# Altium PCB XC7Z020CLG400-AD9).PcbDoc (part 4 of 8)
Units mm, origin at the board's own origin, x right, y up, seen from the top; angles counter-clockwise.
Board outline 38 x 38 mm, 14 copper layers (Top Layer, GND02, ART03, PWR04, ART05, GND06, ART07, ART08, PWR09, ART10, GND11, ART12, PWR13, Bottom Layer); 276 components, 302 nets, 1684 pads, 1576 vias.
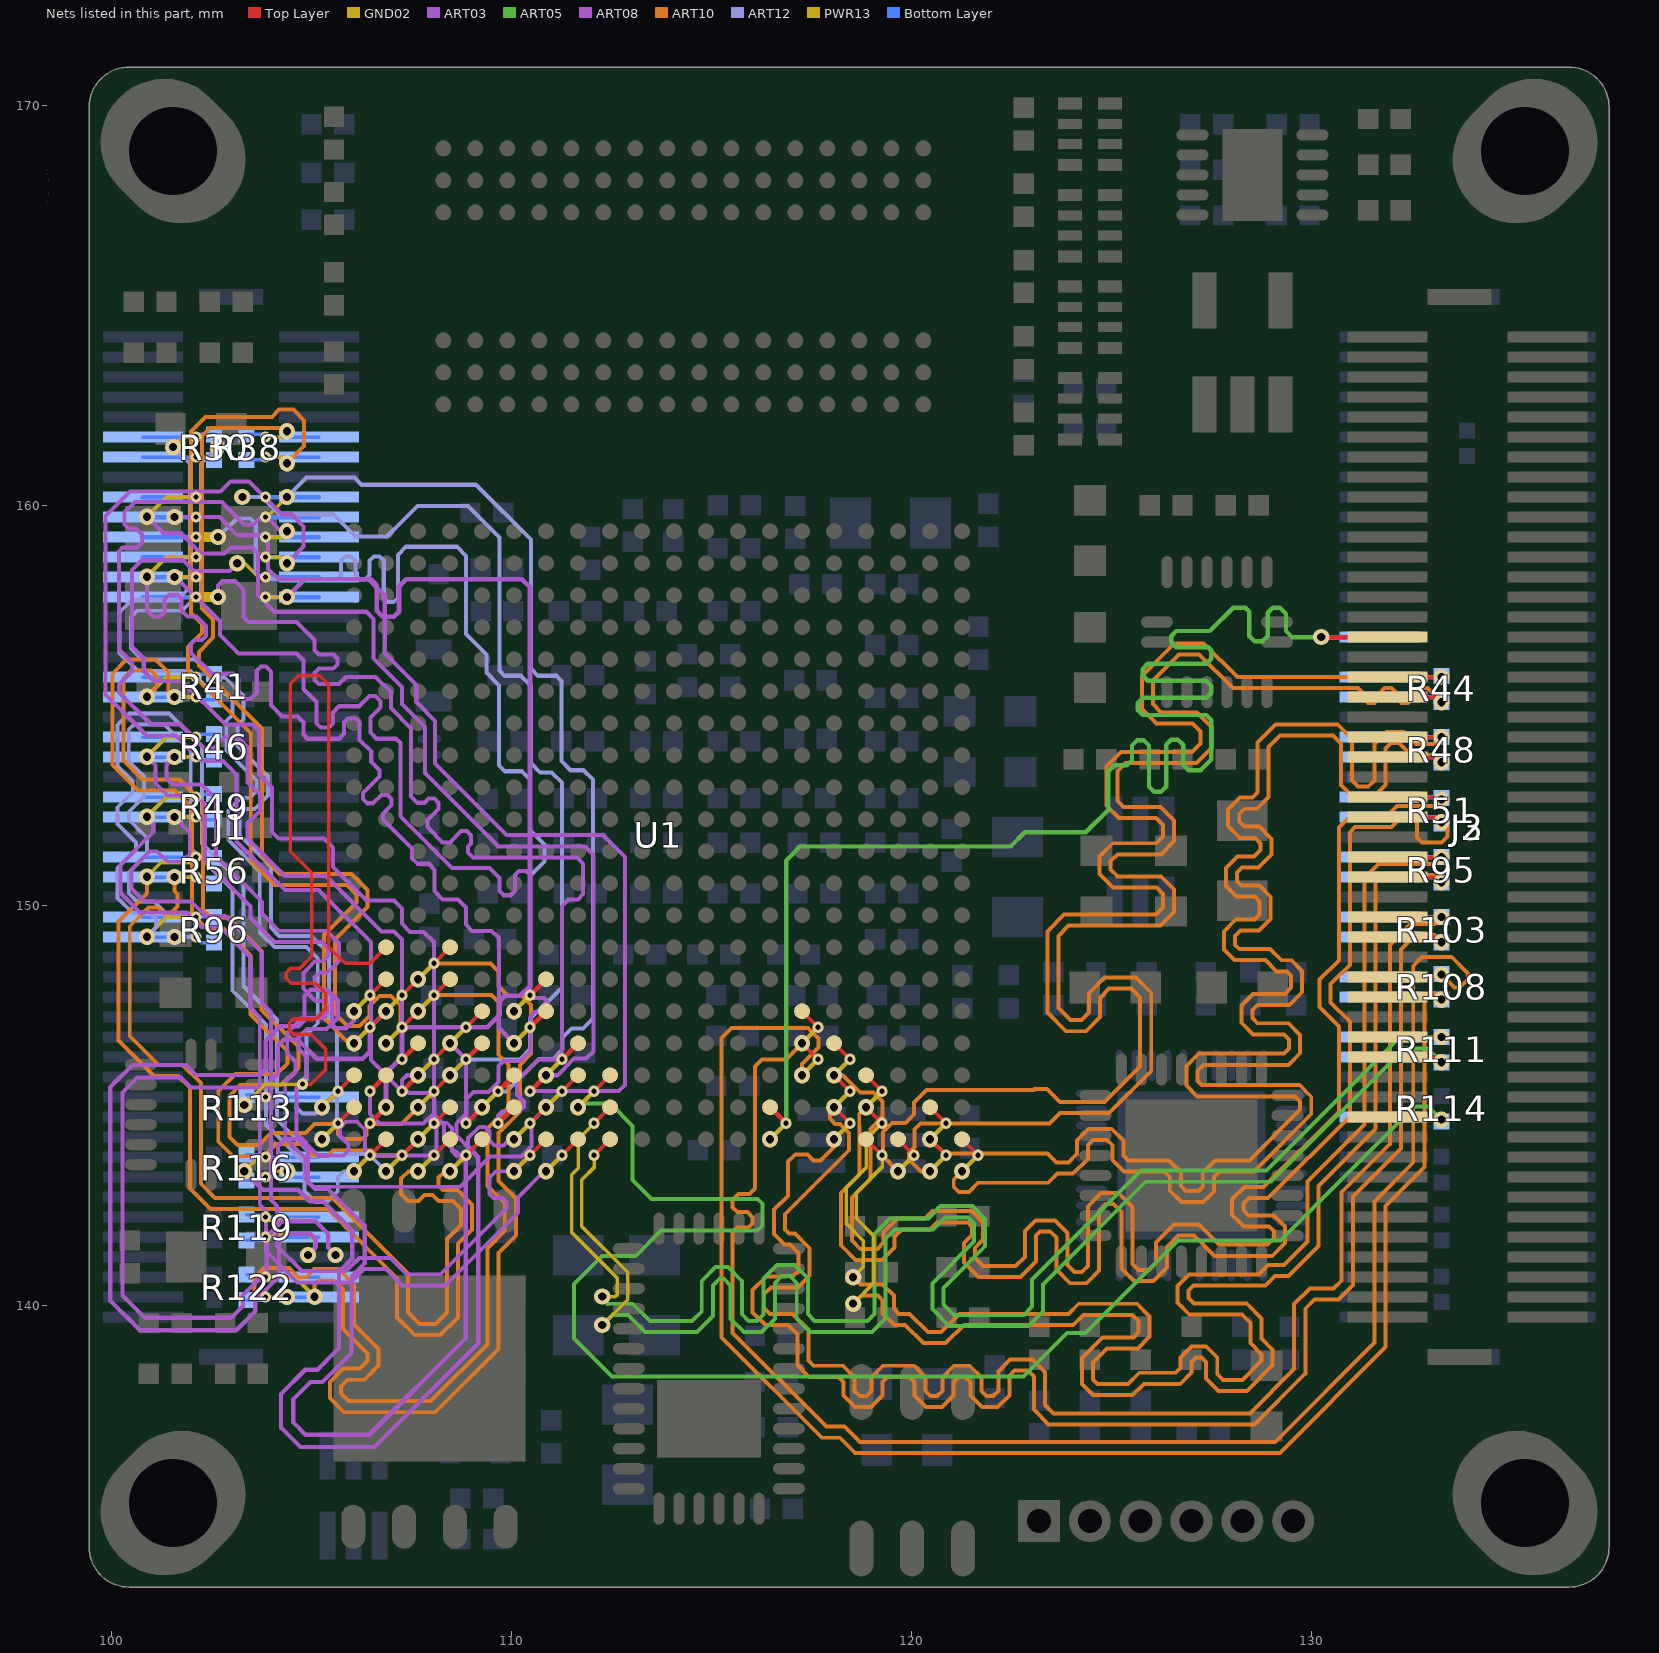
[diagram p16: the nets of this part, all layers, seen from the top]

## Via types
v1: diameter 0.406, hole 0.203, GND02 to PWR13, 466 vias
v2: diameter 0.279, hole 0.127, Top Layer to GND02, tented top, 373 vias
v3: diameter 0.406, hole 0.203, Top Layer to Bottom Layer, 324 vias
v4: diameter 0.279, hole 0.127, PWR13 to Bottom Layer, 207 vias
v5: diameter 0.279, hole 0.127, Top Layer to ART03, tented top, 41 vias
v6: diameter 0.279, hole 0.127, Top Layer to ART03, 40 vias
v7: diameter 0.279, hole 0.127, PWR13 to Bottom Layer, tented bottom, 39 vias
v8: diameter 0.279, hole 0.127, ART12 to Bottom Layer, 30 vias
v9: diameter 0.279, hole 0.127, Top Layer to GND02, 20 vias
v10: diameter 0.406, hole 0.203, Top Layer to Bottom Layer, tented both sides, 16 vias
v11: diameter 0.406, hole 0.203, ART03 to ART12, 11 vias
v12: diameter 0.406, hole 0.203, Top Layer to Bottom Layer, tented top, 9 vias

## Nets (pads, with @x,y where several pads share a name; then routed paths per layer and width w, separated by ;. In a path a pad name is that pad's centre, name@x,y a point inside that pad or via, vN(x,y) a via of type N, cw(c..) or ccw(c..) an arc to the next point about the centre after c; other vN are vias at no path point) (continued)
B34_L8_P: J1.89 R113.1 U1.W14 | length 26.9
  Top Layer w0.089: v9(104.775,145.542) 104.985,145.542 105.362,145.918 ; 105.16,145.716 105.362,145.918 ; U1.W14@106.865,148.965 106.465,148.565 105.842,148.565 105.435,148.971 105.435,155.524 105.207,155.753 104.673,155.753 104.47,155.55 104.47,151.366 105.006,150.83 105.006,148.738 104.703,148.435 104.475,148.435 104.371,148.331 104.371,148.188 104.496,148.064 105.105,148.064 105.358,147.811 105.358,147.421 105.11,147.172 104.551,147.172 104.448,147.07 104.448,146.899 104.554,146.794 104.978,146.794 105.362,146.41 105.362,145.918
  GND02 w0.089: v1(103.32,145.022) 103.841,145.542 v9(104.775,145.542)
  PWR13 w0.089: v1(103.32,145.022) 103.518,145.219 v4(103.853,145.219)
  Bottom Layer w0.089: R113.1@103.378,145.278 103.794,145.278 v4(103.853,145.219) J1.89@105.182,145.219
B34_L9_N: J1.93 R116.2 U1.U17 | length 27
  Top Layer w0.089: v2(108.065,146.165) U1.U17@108.465,146.565
  GND02 w0.109: v1(107.665,145.765) v2(108.065,146.165)
  ART08 w0.107: v1(104.4,143.365) 104.165,143.6 104.165,143.993 104.343,144.17 104.648,144.17 104.907,143.912 104.907,143.105 105.086,142.926 105.416,142.926 106.329,142.013 106.329,141.058 105.999,140.728 105.999,138.816 105.278,138.095 104.973,138.095 104.546,137.668 104.546,137.084 104.851,136.779 106.445,136.779 108.859,139.193 108.859,143.591 108.316,144.135 108.316,144.516 108.077,144.755 108.077,145.161 107.915,145.323 107.432,145.323 107.264,145.491 107.264,145.644 107.386,145.765 v1(107.665,145.765)
  PWR13 w0.089: v4(103.853,143.219) 103.999,143.365 v1(104.4,143.365)
  Bottom Layer w0.089: R116.2@103.378,143.139 103.773,143.139 v4(103.853,143.219) J1.93@105.182,143.219
B34_L9_P: J1.92 R116.1 U1.T16 | length 27
  Top Layer w0.089: v2(108.865,146.965) U1.T16@109.265,147.365
  GND02 w0.109: v1(108.465,146.565) v2(108.865,146.965)
  ART08 w0.107: v1(103.32,143.365) 103.78,142.905 104.669,142.905 104.958,142.616 105.288,142.616 106.02,141.884 106.02,141.186 105.75,140.917 105.706,140.917 105.689,140.9 105.689,138.944 105.15,138.405 104.845,138.405 104.237,137.796 104.237,136.955 104.723,136.469 106.573,136.469 109.169,139.065 109.169,143.72 108.626,144.263 108.626,144.556 108.864,144.795 108.864,146.166 v1(108.465,146.565)
  PWR13 w0.089: v1(103.32,143.365) 103.675,143.719 v4(103.853,143.719)
  Bottom Layer w0.089: R116.1@103.378,143.779 103.793,143.779 v4(103.853,143.719) J1.92@105.182,143.719
B34_L10_N: J1.96 R119.2 U1.W15 | length 26.9
  Top Layer w0.089: v2(106.465,147.765) U1.W15@106.865,148.165
  GND02 w0.109: v1(106.065,147.365) v2(106.465,147.765)
  ART08 w0.107: v1(104.914,141.275) 105.105,141.466 105.105,141.675 104.977,141.803 104.389,141.803 104.191,141.605 104.191,140.735 103.597,140.141 103.597,139.868 103.119,139.39 100.71,139.39 99.967,140.133 99.967,145.465 100.522,146.02 101.865,146.02 102.114,145.771 103.703,145.771 103.856,145.923 103.856,146.636 104.21,146.99 104.673,146.99 104.826,147.142 104.826,147.752 104.978,147.904 105.359,147.904 105.512,147.752 105.512,147.041 105.613,146.939 105.867,146.939 106.065,147.137 v1(106.065,147.365)
  PWR13 w0.089: v4(103.853,141.719) 103.932,141.798 104.926,141.798 105.087,141.637 105.087,141.448 v1(104.914,141.275)
  Bottom Layer w0.089: R119.2@103.378,141.641 103.774,141.641 v4(103.853,141.719) J1.96@105.182,141.719
B34_L10_P: J1.95 R119.1 U1.V15 | length 26.9
  Top Layer w0.089: v2(107.265,147.765) U1.V15@107.665,148.165
  GND02 w0.109: v1(106.865,147.365) v2(107.265,147.765)
  ART08 w0.107: v1(105.602,141.275) 105.415,141.462 105.415,141.803 105.105,142.113 104.261,142.113 103.881,141.733 103.881,140.863 103.287,140.27 103.287,139.997 102.991,139.7 100.838,139.7 100.277,140.261 100.277,145.336 100.651,145.71 101.736,145.71 101.986,145.461 103.831,145.461 104.165,145.795 104.165,146.507 104.318,146.66 104.648,146.66 105.131,146.177 106.274,146.177 106.451,146.355 106.451,146.951 v1(106.865,147.365)
  PWR13 w0.089: v4(103.853,142.219) 103.932,142.141 105.068,142.141 105.43,141.779 105.43,141.448 v1(105.602,141.275)
  Bottom Layer w0.089: R119.1@103.378,142.281 103.792,142.281 v4(103.853,142.219) J1.95@105.182,142.219
B34_L11_N: J1.99 R122.2 U1.U15 | length 27.1
  Top Layer w0.089: v2(108.065,147.765) U1.U15@108.465,148.165
  ART10 w0.099: v1(104.391,140.219) 103.722,140.219 103.581,140.36 103.581,140.716 103.81,140.945 104.445,140.945 104.673,140.716 104.866,140.716 105.067,140.917 105.677,140.917 106.068,140.526 106.068,139.535 106.68,138.923 106.68,138.506 106.327,138.153 105.906,138.153 105.738,137.985 105.738,137.808 105.929,137.617 107.975,137.617 109.398,139.04 109.398,141.438 109.832,141.872 109.832,142.568 109.398,143.002 109.398,144.435 109.931,144.968 109.931,146.025 ; v1(107.665,147.365) 108.077,147.777 109.499,147.777 109.677,147.599 109.677,146.279 109.931,146.025 ; 109.931,145.999 109.931,146.025
  GND02 w0.109: v1(107.665,147.365) v2(108.065,147.765)
  PWR13 w0.102: v4(103.853,140.219) v1(104.391,140.219)
  Bottom Layer w0.089: R122.2@103.378,140.142 103.776,140.142 v4(103.853,140.219) J1.99@105.182,140.219
B34_L11_P: J1.98 R122.1 U1.U14 | length 27.1
  Top Layer w0.089: v2(108.065,148.565) U1.U14@108.465,148.965
  ART10 w0.099: v1(105.079,140.23) 105.079,140.537 105.181,140.64 105.562,140.64 105.791,140.411 105.791,139.421 106.403,138.808 106.403,138.621 106.212,138.43 105.791,138.43 105.461,138.1 105.461,137.693 105.814,137.34 108.09,137.34 109.675,138.925 109.675,141.323 110.109,141.757 110.109,142.682 109.675,143.117 109.675,144.32 110.208,144.854 110.208,146.025 110.49,146.307 110.49,147.523 110.261,147.752 109.916,147.752 109.677,147.991 109.677,148.361 109.474,148.565 v2(108.065,148.565) v1(107.665,148.165)
  GND02 w0.109: v1(107.665,148.165) v2(108.065,148.565)
  PWR13 w0.102: v4(103.853,140.719) 104.589,140.719 v1(105.079,140.23)
  Bottom Layer w0.089: R122.1@103.378,140.782 103.79,140.782 v4(103.853,140.719) J1.98@105.182,140.719
B34_L12_N: J1.19 R41.2 U1.U19 | length 27.1
  Top Layer w0.089: v2(108.065,144.565) U1.U19@108.465,144.965
  ART10 w0.099: v1(101.573,155.219) 101.42,155.373 101.42,155.842 101.105,156.157 100.378,156.157 100.025,155.804 100.025,153.518 100.66,152.883 101.589,152.883 102.009,152.463 102.009,149.796 102.374,149.431 102.806,149.431 103.478,148.759 103.478,147.285 104.397,146.367 104.397,146.063 104.127,145.793 103.096,145.793 102.669,145.367 102.669,144.107 103.035,143.741 103.797,143.741 104.1,144.043 104.775,144.043 105.054,143.764 105.41,143.764 105.537,143.891 106.502,143.891 106.629,143.764 107.264,143.764 v1(107.665,144.165)
  GND02 w0.109: v1(107.665,144.165) v2(108.065,144.565)
  PWR13 w0.102: v1(101.573,155.219) v4(102.111,155.219)
  Bottom Layer w0.089: J1.19@100.782,155.219 v4(102.111,155.219) 102.177,155.153 R41.2@102.565,155.153
B34_L12_P: J1.18 R41.1 U1.U18 | length 27
  Top Layer w0.089: v2(108.065,145.365) U1.U18@108.465,145.765
  ART10 w0.099: v1(100.885,155.23) 101.143,155.487 101.143,155.727 100.99,155.88 100.493,155.88 100.302,155.689 100.302,153.632 100.775,153.159 101.704,153.159 102.286,152.578 102.286,149.911 102.489,149.708 102.921,149.708 103.755,148.873 103.755,147.4 104.673,146.482 104.673,145.948 104.242,145.517 103.211,145.517 102.946,145.252 102.946,144.221 103.149,144.018 103.683,144.018 103.985,144.32 104.849,144.32 105.08,144.551 105.512,144.551 105.664,144.399 105.664,144.297 105.794,144.168 106.271,144.168 106.375,144.272 106.375,144.45 106.477,144.551 107.251,144.551 v1(107.665,144.965)
  GND02 w0.109: v1(107.665,144.965) v2(108.065,145.365)
  PWR13 w0.102: v1(100.885,155.23) 101.375,155.719 v4(102.111,155.719)
  Bottom Layer w0.089: J1.18@100.782,155.719 v4(102.111,155.719) 102.185,155.793 R41.1@102.565,155.793
B34_L13_N: J1.22 R46.2 U1.P19 | length 27
  Top Layer w0.089: v2(110.465,144.565) U1.P19@110.865,144.965
  ART03 w0.097: v1(101.573,153.719) 101.378,153.524 101.378,153.181 101.524,153.035 102.249,153.035 102.616,152.668 102.616,151.246 103.759,150.103 103.759,149.809 104.191,149.377 105.373,149.377 105.689,149.061 105.689,148.627 105.399,148.336 105.207,148.336 105.08,148.209 105.08,148.045 105.221,147.904 105.399,147.904 105.664,147.639 105.664,147.204 105.378,146.918 104.881,146.918 104.673,146.71 104.673,146.431 104.877,146.228 104.877,145.731 104.623,145.477 104.623,144.308 105.167,143.764 105.8,143.764 105.924,143.888 105.924,144.037 105.715,144.247 105.715,144.45 105.867,144.602 106.138,144.602 106.338,144.402 106.338,143.888 106.463,143.764 108.026,143.764 108.128,143.866 108.128,144.475 108.229,144.577 108.382,144.577 108.509,144.45 108.509,143.866 108.61,143.764 108.788,143.764 108.915,143.891 108.915,144.196 109.195,144.475 109.345,144.475 109.449,144.372 109.449,144.137 109.576,144.01 109.796,144.01 109.951,144.165 v1(110.065,144.165)
  GND02 w0.109: v1(110.065,144.165) v2(110.465,144.565)
  PWR13 w0.102: v1(101.573,153.719) v4(102.111,153.719)
  Bottom Layer w0.089: J1.22@100.782,153.719 v4(102.111,153.719) 102.175,153.655 R46.2@102.565,153.655
B34_L13_P: J1.21 R46.1 U1.N18 | length 27
  Top Layer w0.089: v2(111.265,145.365) U1.N18@111.665,145.765
  ART03 w0.097: v1(100.885,153.73) 101.099,153.516 101.099,153.065 101.408,152.756 102.133,152.756 102.337,152.552 102.337,151.13 103.48,149.987 103.48,149.693 104.075,149.098 105.258,149.098 105.41,148.946 105.41,148.742 105.283,148.615 105.091,148.615 104.8,148.325 104.8,147.93 105.105,147.625 105.283,147.625 105.385,147.523 105.385,147.32 105.262,147.197 104.765,147.197 104.394,146.826 104.394,146.315 104.597,146.112 104.597,145.847 104.343,145.593 104.343,144.192 104.851,143.684 104.851,143.18 105.054,142.977 108.712,142.977 109.466,143.731 110.245,143.731 110.499,143.985 110.499,144.345 110.497,144.347 110.497,144.597 v1(110.865,144.965)
  GND02 w0.109: v1(110.865,144.965) v2(111.265,145.365)
  PWR13 w0.102: v1(100.885,153.73) 101.375,154.219 v4(102.111,154.219)
  Bottom Layer w0.089: J1.21@100.782,154.219 v4(102.111,154.219) 102.187,154.295 R46.1@102.565,154.295
B34_L14_N: J1.25 R49.2 U1.P20 | length 27
  Top Layer w0.089: v2(110.465,143.765) U1.P20@110.865,144.165
  ART03 w0.097: v1(101.573,152.219) 101.956,151.837 101.956,151.282 101.778,151.105 101.397,151.105 101.143,151.359 100.954,151.359 100.502,150.907 100.502,150.439 100.827,150.114 101.995,150.114 102.363,149.746 102.841,149.746 103.759,148.828 103.759,147.574 103.988,147.345 103.988,142.646 104.14,142.494 104.14,141.492 104.764,140.868 105.867,140.868 106.197,141.199 106.974,141.199 107.38,140.792 108.229,140.792 109.88,142.443 109.88,142.596 109.779,142.697 109.55,142.697 109.449,142.799 109.449,143.205 109.608,143.365 v1(110.065,143.365)
  GND02 w0.109: v1(110.065,143.365) v2(110.465,143.765)
  PWR13 w0.102: v1(101.573,152.219) v4(102.111,152.219)
  Bottom Layer w0.089: J1.25@100.782,152.219 v4(102.111,152.219) 102.174,152.156 R49.2@102.565,152.156
B34_L14_P: J1.24 R49.1 U1.N20 | length 27.1
  Top Layer w0.089: v2(111.265,143.765) U1.N20@111.665,144.165
  ART03 w0.097: v1(100.885,152.23) 101.041,152.073 101.041,151.841 100.223,151.023 100.223,150.323 100.711,149.835 101.879,149.835 102.248,149.466 102.725,149.466 103.48,148.712 103.48,147.458 103.708,147.23 103.708,142.531 103.861,142.378 103.861,141.376 104.648,140.589 105.983,140.589 106.313,140.919 106.858,140.919 107.264,140.513 108.345,140.513 110.16,142.327 110.16,142.708 110.816,143.365 v1(110.865,143.365)
  GND02 w0.109: v1(110.865,143.365) v2(111.265,143.765)
  PWR13 w0.102: v1(100.885,152.23) 101.375,152.719 v4(102.111,152.719)
  Bottom Layer w0.089: J1.24@100.782,152.719 v4(102.111,152.719) 102.188,152.796 R49.1@102.565,152.796
B34_L15_N: J1.28 R56.2 U1.U20 | length 27
  Top Layer w0.089: v2(108.065,143.765) U1.U20@108.465,144.165
  ART10 w0.099: v1(101.573,150.719) 101.573,150.369 101.651,150.292 101.651,149.987 101.473,149.809 101.321,149.809 101.226,149.904 101.168,149.962 100.928,149.962 100.457,149.49 100.457,146.746 101.181,146.022 101.78,146.022 102.235,145.567 102.235,143.053 102.593,142.695 105.525,142.695 107.414,140.805 107.414,139.83 107.696,139.548 108.102,139.548 108.384,139.83 108.384,141.669 108.737,142.022 108.737,142.418 108.534,142.621 108.179,142.621 108.026,142.773 107.823,142.773 107.671,142.621 107.417,142.621 107.239,142.799 107.239,143.18 107.424,143.365 v1(107.665,143.365)
  GND02 w0.109: v1(107.665,143.365) v2(108.065,143.765)
  PWR13 w0.089: v1(101.573,150.719) v4(102.111,150.719)
  Bottom Layer w0.089: J1.28@100.782,150.719 v4(102.111,150.719) 102.274,150.556 R56.2@102.565,150.556
B34_L15_P: J1.27 R56.1 U1.T20 | length 27
  Top Layer w0.089: v2(108.865,143.765) U1.T20@109.265,144.165
  ART10 w0.099: v1(100.885,150.73) 100.885,150.313 100.18,149.609 100.18,146.632 101.067,145.745 101.666,145.745 101.958,145.453 101.958,142.938 102.478,142.418 105.41,142.418 107.137,140.691 107.137,139.715 107.581,139.271 108.217,139.271 108.661,139.715 108.661,141.554 109.014,141.907 109.014,142.532 108.649,142.898 108.293,142.898 108.179,143.013 108.179,143.205 108.338,143.365 v1(108.465,143.365)
  GND02 w0.109: v1(108.465,143.365) v2(108.865,143.765)
  PWR13 w0.089: v1(100.885,150.73) 101.235,151.079 101.971,151.079 v4(102.111,151.219)
  Bottom Layer w0.089: J1.27@100.782,151.219 v4(102.111,151.219) 102.134,151.196 R56.1@102.565,151.196
B34_L16_N: J1.31 R96.2 U1.W20 | length 27
  Top Layer w0.089: v2(106.465,143.765) U1.W20@106.865,144.165
  ART12 w0.097: v1(101.573,149.219) 101.975,149.219 102.083,149.327 102.083,149.657 101.928,149.812 101.369,149.812 101.067,150.114 100.635,150.114 100.432,150.317 100.432,150.836 100.889,151.294 100.889,151.703 100.432,152.16 100.432,152.349 100.813,152.73 100.813,153.238 100.432,153.619 100.432,154.407 100.559,154.534 101.321,154.534 101.981,153.873 101.981,151.446 103.022,150.405 103.022,147.879 103.861,147.041 103.861,144.537 104.826,143.572 104.826,142.875 105.105,142.596 105.385,142.596 105.658,142.869 105.658,143.205 105.817,143.365 v1(106.065,143.365)
  GND02 w0.109: v1(106.065,143.365) v2(106.465,143.765)
  PWR13 w0.102: v1(101.573,149.219) v4(102.111,149.219)
  Bottom Layer w0.089: J1.31@100.782,149.219 v4(102.111,149.219) 102.247,149.083 R96.2@102.565,149.083
B34_L16_P: J1.30 R96.1 U1.V20 | length 27.1
  Top Layer w0.089: v2(107.265,143.765) U1.V20@107.665,144.165
  ART12 w0.097: v1(100.885,149.23) 101.117,149.462 101.117,149.668 100.951,149.835 100.519,149.835 100.152,150.201 100.152,150.952 100.609,151.409 100.609,151.587 100.152,152.044 100.152,152.465 100.533,152.846 100.533,153.122 100.152,153.503 100.152,154.522 100.443,154.813 101.436,154.813 102.26,153.989 102.26,151.562 103.302,150.52 103.302,147.995 104.14,147.156 104.14,144.653 105.029,143.764 105.85,143.764 105.885,143.799 106.431,143.799 v1(106.865,143.365)
  GND02 w0.109: v1(106.865,143.365) v2(107.265,143.765)
  PWR13 w0.102: v1(100.885,149.23) 101.375,149.719 v4(102.111,149.719)
  Bottom Layer w0.089: J1.30@100.782,149.719 v4(102.111,149.719) 102.115,149.723 R96.1@102.565,149.723
B34_L17_N: J1.7 R30.2 U1.Y19 | length 27
  Top Layer w0.089: v2(105.665,144.565) U1.Y19@106.065,144.965
  ART12 w0.097: v1(102.649,161.468) 102.235,161.054 102.235,157.847 101.767,157.378 100.635,157.378 100.482,157.226 100.482,156.439 100.762,156.159 102.083,156.159 102.54,155.702 102.845,155.702 103.302,155.245 103.302,154.661 103.149,154.508 103.149,154 103.911,153.238 103.911,152.756 103.581,152.425 103.353,152.425 103.2,152.273 103.2,151.765 103.988,150.978 103.988,149.454 104.191,149.25 104.992,149.25 105.435,148.807 105.435,147.117 105.639,146.914 105.639,144.539 v1(105.265,144.165)
  GND02 w0.109: v1(105.265,144.165) v2(105.665,144.565)
  PWR13 w0.089: v4(102.111,161.219) 102.4,161.219 v1(102.649,161.468)
  Bottom Layer w0.089: J1.7@100.782,161.219 v4(102.111,161.219) 102.182,161.148 R30.2@102.565,161.148
B34_L17_P: J1.6 R30.1 U1.Y18 | length 27
  Top Layer w0.089: v2(105.665,145.365) U1.Y18@106.065,145.765
  ART12 w0.097: v1(101.542,161.468) 101.956,161.055 101.956,157.963 101.651,157.658 100.519,157.658 100.203,157.342 100.203,156.323 100.646,155.88 101.967,155.88 102.424,155.423 102.729,155.423 103.022,155.129 103.022,154.776 102.87,154.624 102.87,153.884 103.632,153.122 103.632,152.871 103.465,152.705 103.237,152.705 102.921,152.389 102.921,151.649 103.708,150.862 103.708,149.338 104.075,148.971 104.877,148.971 105.156,148.692 105.156,147.066 104.877,146.787 104.877,145.644 104.623,145.39 104.623,144.958 104.775,144.805 105.105,144.805 v1(105.265,144.965)
  GND02 w0.109: v1(105.265,144.965) v2(105.665,145.365)
  PWR13 w0.089: v1(101.542,161.468) 101.794,161.719 v4(102.111,161.719)
  Bottom Layer w0.089: J1.6@100.782,161.719 v4(102.111,161.719) 102.18,161.788 R30.1@102.565,161.788
B34_L18_N: J1.57 R38.2 U1.W16 | length 27.1
  Top Layer w0.089: v2(106.465,146.965) U1.W16@106.865,147.365
  ART10 w0.099: v1(104.386,161.065) 104.816,161.496 104.816,162.138 104.546,162.408 104.191,162.408 104.01,162.227 102.349,162.227 101.984,161.862 101.984,157.325 102.26,157.048 102.26,156.82 101.907,156.467 101.907,155.892 103.482,154.317 103.482,151.127 104.089,150.52 105.882,150.52 106.124,150.279 106.124,150.087 105.308,149.271 105.308,147.193 105.936,146.565 v1(106.065,146.565)
  GND02 w0.109: v1(106.065,146.565) v2(106.465,146.965)
  PWR13 w0.089: v4(103.853,161.219) 104.231,161.219 v1(104.386,161.065)
  Bottom Layer w0.089: R38.2@103.378,161.148 103.782,161.148 v4(103.853,161.219) J1.57@105.182,161.219
B34_L18_P: J1.56 R38.1 U1.V16 | length 27.1
  Top Layer w0.089: v2(107.265,146.965) U1.V16@107.665,147.365
  ART10 w0.099: v1(104.386,161.865) 104.3,161.95 102.464,161.95 102.26,161.747 102.26,157.44 102.537,157.163 102.537,156.705 102.184,156.352 102.184,156.007 103.759,154.432 103.759,151.242 104.204,150.797 105.997,150.797 106.401,150.393 106.401,149.972 105.585,149.157 105.585,147.308 105.897,146.996 106.203,146.996 106.451,147.244 106.451,147.498 106.705,147.752 106.985,147.752 107.219,147.517 107.219,146.919 v1(106.865,146.565)
  GND02 w0.109: v1(106.865,146.565) v2(107.265,146.965)
  PWR13 w0.089: v4(103.853,161.719) 104.24,161.719 v1(104.386,161.865)
  Bottom Layer w0.089: R38.1@103.378,161.788 103.784,161.788 v4(103.853,161.719) J1.56@105.182,161.719
B34_S0: J1.59 U1.T17 | length 27
  Top Layer w0.114: v2(108.865,146.165) U1.T17@109.265,146.565
  ART12 w0.102: v1(103.272,160.219) 103.763,160.219 104.191,159.791 105.537,159.791 106.096,159.233 106.883,159.233 107.645,159.995 108.915,159.995 109.703,159.207 109.703,155.88 109.83,155.753 110.236,155.753 110.49,155.499 110.49,153.568 110.719,153.34 111.004,153.34 111.258,153.086 111.258,147.961 110.465,147.168 110.465,146.419 110.211,146.165 v2(108.865,146.165) v1(108.465,145.765)
  GND02 w0.109: v1(108.465,145.765) v2(108.865,146.165)
  PWR13 w0.089: v1(103.272,160.219) v4(103.853,160.219)
  Bottom Layer w0.114: v4(103.853,160.219) J1.59@105.182,160.219
B34_S1: J1.60 U1.R18 | length 27.1
  Top Layer w0.114: v2(109.665,145.365) U1.R18@110.065,145.765
  ART12 w0.102: v1(104.386,160.219) 104.872,160.706 106.07,160.706 106.248,160.528 109.118,160.528 110.49,159.156 110.49,155.931 110.668,155.753 111.125,155.753 111.252,155.626 111.252,153.619 111.481,153.391 111.805,153.391 112.034,153.162 112.034,147.187 111.785,146.939 111.506,146.939 111.277,146.71 111.277,146.406 111.049,146.177 110.693,146.177 109.875,145.359 109.659,145.359 v1(109.265,144.965)
  GND02 w0.109: v1(109.265,144.965) v2(109.665,145.365)
  PWR13 w0.089: v4(103.853,159.719) 103.886,159.719 v1(104.386,160.219)
  Bottom Layer w0.114: v4(103.853,159.719) J1.60@105.182,159.719
B34_S2: J1.61 U1.V17 | length 27
  Top Layer w0.114: v5(107.265,146.165) U1.V17@107.665,146.565
  ART03 w0.102: v1(104.386,159.365) 104.236,159.365 103.92,159.681 103.699,159.681 103.556,159.537 103.316,159.537 102.757,160.096 100.584,160.096 100.33,159.842 100.33,159.538 100.432,159.436 100.609,159.436 100.762,159.283 100.762,159.08 100.635,158.953 100.279,158.953 100.184,158.858 100.184,156.413 100.508,156.09 100.508,155.861 100.184,155.538 100.184,155.34 100.983,154.541 101.72,154.541 102.311,153.949 102.565,153.949 102.84,154.224 103.154,154.224 103.403,153.975 103.403,153.086 103.708,152.781 103.708,152.375 103.403,152.07 103.403,151.689 104.343,150.749 105.359,150.749 106.749,149.359 107.068,149.359 107.265,149.162 v5(107.265,146.165)
  PWR13 w0.089: v4(103.853,159.219) 104.24,159.219 v1(104.386,159.365)
  Bottom Layer w0.114: v4(103.853,159.219) J1.61@105.182,159.219
B34_S3: J1.62 U1.V18 | length 28
  Top Layer w0.114: v5(107.265,145.365) U1.V18@107.665,145.765
  ART03 w0.102: v1(104.386,158.565) 104.8,158.98 104.8,159.487 104.496,159.791 104.255,159.791 103.436,160.611 102.972,160.611 102.72,160.36 100.467,160.36 99.854,159.747 99.854,155.289 100.882,154.261 101.618,154.261 102.26,153.619 102.794,153.619 103.124,153.289 103.124,151.613 104.343,150.393 105.181,150.393 106.484,149.091 106.484,146.146 v5(107.265,145.365)
  PWR13 w0.089: v4(103.853,158.719) 104.231,158.719 v1(104.386,158.565)
  Bottom Layer w0.114: v4(103.853,158.719) J1.62@105.182,158.719
B34_S4: J1.63 U1.W18 | length 26.8
  Top Layer w0.114: v5(106.465,145.365) U1.W18@106.865,145.765
  ART03 w0.102: v1(103.145,158.565) 102.956,158.376 102.064,158.376 101.792,158.648 100.762,158.648 100.515,158.401 100.515,156.483 100.807,156.19 100.807,155.874 101.055,155.626 101.752,155.626 102.845,154.534 103.53,154.534 103.69,154.374 103.69,153.289 104.016,152.962 104.016,151.845 104.172,151.689 105.308,151.689 105.537,151.46 105.537,150.978 106.375,150.139 107.061,150.139 107.264,149.936 107.264,149.555 107.467,149.352 107.804,149.352 108.058,149.098 108.058,144.812 107.805,144.558 106.698,144.558 106.465,144.792 v5(106.465,145.365)
  PWR13 w0.089: v1(103.145,158.565) 103.336,158.565 103.682,158.219 v4(103.853,158.219)
  Bottom Layer w0.114: v4(103.853,158.219) J1.63@105.182,158.219
B34_S5: J1.64 U1.W19 | length 26.8
  Top Layer w0.114: v2(106.465,144.565) v1(106.865,144.965)
  GND02 w0.102: v2(106.465,144.565) v1(106.865,144.965)
  ART08 w0.119: v1(104.386,157.719) 104.832,158.166 106.477,158.166 106.629,158.013 106.629,157.378 106.782,157.226 107.061,157.226 107.188,157.353 107.188,157.988 107.366,158.166 110.261,158.166 110.465,157.963 110.465,148.006 110.211,147.752 109.83,147.752 109.701,147.623 109.701,147.267 109.398,146.964 107.391,146.964 107.264,146.837 107.264,146.228 106.865,145.829 v1(106.865,144.965)
  PWR13 w0.089: v4(103.853,157.719) v1(104.386,157.719)
  Bottom Layer w0.114: v4(103.853,157.719) J1.64@105.182,157.719
B34_S6: J1.9 U1.N17 | length 27.2
  Top Layer w0.114: v2(111.265,146.165) U1.N17@111.665,146.565
  ART03 w0.102: v1(100.885,159.73) 101.299,159.316 101.734,159.316 102.242,158.808 102.826,158.808 102.978,158.96 103.512,158.96 103.664,158.808 103.664,157.766 104.078,157.353 106.375,157.353 106.553,157.175 106.553,156.185 ; 106.553,156.261 106.553,156.185 ; v1(110.865,145.765) 111.145,145.765 111.564,146.184 111.868,146.184 112.046,146.362 112.046,151.276 111.836,151.486 109.677,151.486 107.836,153.327 107.836,154.47 107.264,155.042 107.264,155.473 106.553,156.185
  GND02 w0.109: v1(110.865,145.765) v2(111.265,146.165)
  PWR13 w0.102: v1(100.885,159.73) 101.375,160.219 v4(102.111,160.219)
  Bottom Layer w0.114: J1.9@100.782,160.219 v4(102.111,160.219)
B34_S7: J1.10 U1.P18 | length 27.4
  Top Layer w0.114: v5(110.465,145.365) U1.P18@110.865,145.765
  ART03 w0.102: v1(101.573,159.719) 102.702,159.719 103.156,159.265 103.715,159.265 103.918,159.062 103.918,158.427 104.172,158.173 106.419,158.173 106.832,157.759 106.832,156.312 107.62,155.524 107.62,155.092 108.09,154.623 108.09,153.556 109.873,151.772 112.286,151.772 112.834,151.225 112.834,145.523 112.681,145.371 110.471,145.371 v5(110.465,145.365)
  PWR13 w0.102: v1(101.573,159.719) v4(102.111,159.719)
  Bottom Layer w0.114: J1.10@100.782,159.719 v4(102.111,159.719)
B34_S8: J1.11 U1.P15 | length 27.2
  Top Layer w0.114: v2(110.465,147.765) U1.P15@110.865,148.165
  ART12 w0.102: v1(102.665,159.219) 103.136,159.69 103.48,159.69 103.607,159.563 103.607,158.344 103.784,158.166 105.634,158.166 105.74,158.273 105.74,158.631 105.847,158.738 105.989,158.738 106.096,158.631 106.096,158.273 106.202,158.166 106.345,158.166 106.451,158.273 106.451,158.631 106.558,158.738 106.7,158.738 106.807,158.631 106.807,157.701 106.914,157.595 107.056,157.595 107.163,157.701 107.163,158.775 107.366,158.979 108.636,158.979 108.864,158.75 108.864,156.794 109.372,156.286 109.372,155.829 109.693,155.508 109.693,153.508 109.836,153.365 110.261,153.365 110.465,153.162 110.465,151.892 110.82,151.536 110.82,151.105 110.465,150.749 v2(110.465,147.765) v1(110.065,147.365)
  GND02 w0.109: v1(110.065,147.365) v2(110.465,147.765)
  PWR13 w0.254: v4(102.111,159.219) v1(102.665,159.219)
  Bottom Layer w0.114: J1.11@100.782,159.219 v4(102.111,159.219)
B34_S9: J1.12 U1.P16 | length 26.9
  Top Layer w0.114: v2(110.465,146.965) U1.P16@110.865,147.365
  ART03 w0.102: v1(100.885,158.23) 100.885,157.382 101.037,157.231 101.219,157.231 101.321,157.332 101.321,157.658 101.448,157.785 101.651,157.785 101.752,157.683 101.752,157.383 101.905,157.231 102.129,157.231 102.362,156.997 102.362,156.743 102.26,156.642 102.083,156.642 101.981,156.54 101.981,156.337 102.514,155.804 103.048,155.804 103.175,155.677 103.175,155.296 103.302,155.169 103.48,155.169 103.632,155.321 103.632,155.88 103.734,155.981 103.861,155.981 103.988,155.854 103.988,155.016 104.267,154.737 104.648,154.737 104.8,154.584 104.8,154.28 104.902,154.178 105.689,154.178 105.816,154.305 105.816,154.584 105.918,154.686 106.096,154.686 106.197,154.584 106.197,154.153 106.495,153.855 106.495,153.601 106.705,153.391 106.705,153.237 106.411,152.943 106.286,152.818 106.286,152.667 106.387,152.566 106.538,152.566 106.746,152.775 106.897,152.775 106.997,152.674 106.997,152.523 106.789,152.315 106.789,152.164 107.518,151.435 107.518,151.181 107.645,151.054 107.925,151.054 108.077,150.901 108.077,150.368 108.28,150.165 108.661,150.165 108.864,149.962 108.864,149.53 109.017,149.377 109.499,149.377 109.684,149.193 109.684,146.946 v1(110.065,146.565)
  GND02 w0.109: v1(110.065,146.565) v2(110.465,146.965)
  PWR13 w0.102: v1(100.885,158.23) 101.375,158.719 v4(102.111,158.719)
  Bottom Layer w0.114: J1.12@100.782,158.719 v4(102.111,158.719)
B34_S10: J1.13 U1.T19 | length 26.9
  Top Layer w0.114: v5(108.865,144.565) U1.T19@109.265,144.965
  ART03 w0.102: v1(101.573,158.219) 101.605,158.219 102.709,157.116 102.709,156.778 103.175,156.312 104.623,156.312 104.8,156.134 104.8,155.423 105.131,155.092 105.131,154.559 105.232,154.457 105.435,154.457 105.537,154.559 105.537,154.838 105.689,154.991 106.194,154.991 106.448,155.245 106.604,155.245 106.731,155.118 106.731,154.965 106.477,154.711 106.477,154.33 106.629,154.178 107.112,154.178 107.221,154.069 107.221,152.24 108.509,150.952 109.449,150.952 109.703,150.698 109.703,150.368 109.804,150.266 109.982,150.266 110.084,150.368 110.084,150.774 110.185,150.876 110.363,150.876 110.471,150.768 110.471,147.808 110.578,147.701 110.809,147.701 110.916,147.594 110.916,147.452 110.809,147.345 110.578,147.345 110.471,147.239 110.471,146.387 110.21,146.126 109.804,146.126 109.677,145.999 109.677,145.593 109.43,145.346 109.049,145.346 108.871,145.168 v5@108.871,144.571
  PWR13 w0.102: v1(101.573,158.219) v4(102.111,158.219)
  Bottom Layer w0.114: J1.13@100.782,158.219 v4(102.111,158.219)
B34_S11: J1.14 U1.R19 | length 27.6
  Top Layer w0.114: v5(109.665,144.565) U1.R19@110.065,144.965
  ART03 w0.102: v1(102.665,157.719) 102.665,158.012 102.768,158.115 103.099,158.115 103.302,157.912 103.302,157.226 103.429,157.099 104.623,157.099 105.08,156.642 105.08,156.393 105.186,156.286 105.545,156.286 105.651,156.18 105.651,156.037 105.545,155.931 105.186,155.931 105.08,155.824 105.08,155.651 105.181,155.55 105.689,155.55 105.867,155.727 106.604,155.727 106.985,155.346 106.985,154.948 107.493,154.44 107.493,152.73 107.645,152.578 107.823,152.578 107.925,152.679 108.077,152.679 108.179,152.578 108.179,152.425 107.899,152.146 107.899,151.968 108.28,151.587 108.458,151.587 108.737,151.867 108.89,151.867 108.991,151.765 108.991,151.562 108.915,151.486 108.915,151.333 109.042,151.206 111.633,151.206 111.785,151.054 111.785,150.292 111.658,150.165 111.43,150.165 111.259,149.994 111.259,146.336 111.081,146.159 110.675,146.159 110.134,145.618 110.134,145.283 110.312,145.105 110.312,144.983 110.185,144.856 109.767,144.856 109.665,144.755 v5(109.665,144.565)
  PWR13 w0.254: v4(102.111,157.719) v1(102.665,157.719)
  Bottom Layer w0.114: J1.14@100.782,157.719 v4(102.111,157.719)
B35_C0: J2.85 J3.85 U1.G19 | length 43.5
  Top Layer w0.114: U1.G19@116.465,144.965 v2(116.865,144.565) ; v3(130.243,156.719) J3.85@131.9,156.719
  ART05 w0.109: v1(116.465,144.165) 116.865,144.565 116.865,151.13 117.221,151.486 122.479,151.486 122.834,151.841 124.358,151.841 124.917,152.4 124.917,153.365 125.07,153.518 125.384,153.518 125.512,153.646 125.512,154.009 125.64,154.137 125.81,154.137 125.938,154.009 125.938,152.981 126.066,152.853 126.237,152.853 126.365,152.981 126.365,154.026 126.493,154.154 126.664,154.154 126.792,154.026 126.792,153.523 126.924,153.391 127.229,153.391 127.495,153.657 127.495,154.644 127.367,154.772 125.782,154.772 125.654,154.9 125.654,155.071 125.782,155.199 127.367,155.199 127.495,155.327 127.495,155.498 127.367,155.626 125.908,155.626 125.78,155.754 125.78,155.925 125.908,156.053 127.367,156.053 127.495,156.181 127.495,156.388 127.419,156.464 126.619,156.464 126.492,156.591 126.492,156.743 126.619,156.87 127.457,156.87 128.041,157.455 128.346,157.455 128.448,157.353 128.448,156.743 128.575,156.616 128.778,156.616 128.905,156.743 128.905,157.328 129.032,157.455 129.21,157.455 129.362,157.302 129.362,156.87 129.513,156.719 v3(130.243,156.719)
  GND02 w0.109: v1(116.465,144.165) v2(116.865,144.565)
  Bottom Layer w0.114: v3(130.243,156.719) J2.85@131.7,156.719
B35_L1_N: J2.82 J3.82 R44.1 U1.B20 | length 43.9
  Top Layer w0.089: U1.B20@120.465,144.165 v2(120.865,143.765) ; J3.82@131.9,155.219 133.121,155.219 v3(133.248,155.092)
  ART10 w0.099: v1(120.465,143.365) 120.236,143.365 119.939,143.662 119.939,143.833 120.073,143.967 120.073,144.406 120.225,144.558 123.451,144.558 123.712,144.819 124.942,144.819 125.994,145.872 125.994,147.829 125.616,148.206 124.828,148.206 124.437,147.816 124.437,147.333 124.246,147.142 123.977,147.142 123.673,147.447 123.673,149.25 123.927,149.504 126.223,149.504 126.566,149.847 126.566,150.412 126.238,150.74 125.149,150.74 124.981,150.908 124.981,151.123 125.147,151.289 126.235,151.289 126.566,151.619 126.566,152.134 126.226,152.474 125.301,152.474 125.146,152.629 125.146,153.365 125.349,153.568 127.128,153.568 127.505,153.946 127.505,154.47 127.14,154.836 126.241,154.836 126.035,155.042 126.035,155.637 126.684,156.286 127.189,156.286 128.033,155.442 130.51,155.442 131.165,155.442 131.29,155.317 131.29,155.203 131.415,155.078 131.581,155.078 131.706,155.203 131.706,155.317 131.831,155.442 131.998,155.442 132.123,155.317 132.123,155.203 132.248,155.078 132.414,155.078 132.539,155.203 132.539,155.317 132.664,155.442 132.898,155.442 v3(133.248,155.092)
  GND02 w0.109: v1(120.465,143.365) v2(120.865,143.765)
  Bottom Layer w0.114: J2.82@131.7,155.219 133.121,155.219 v3(133.248,155.092)
B35_L1_P: J2.83 J3.83 R44.2 U1.C20 | length 43.8
  Top Layer w0.089: U1.C20@119.665,144.165 v2(120.065,143.765) ; J3.83@131.9,155.719 v3(133.248,155.719)
  ART10 w0.099: v1(119.665,143.365) 119.285,143.745 119.285,144.348 119.514,144.577 119.852,144.577 120.066,144.791 120.066,145.085 120.378,145.397 123.058,145.397 123.081,145.42 123.388,145.42 123.712,145.096 124.827,145.096 125.717,145.986 125.717,147.714 125.501,147.93 124.943,147.93 124.714,147.701 124.714,147.218 124.361,146.865 123.863,146.865 123.396,147.332 123.396,149.365 123.812,149.781 126.108,149.781 126.289,149.962 126.289,150.297 126.123,150.463 125.034,150.463 124.704,150.794 124.704,151.238 125.032,151.566 126.12,151.566 126.289,151.734 126.289,152.019 126.111,152.197 125.186,152.197 124.869,152.514 124.869,153.48 125.234,153.845 127.013,153.845 127.229,154.061 127.229,154.356 127.025,154.559 126.126,154.559 125.758,154.927 125.758,155.752 126.569,156.563 127.304,156.563 128.148,155.719 v3(133.248,155.719)
  GND02 w0.109: v1(119.665,143.365) v2(120.065,143.765)
  Bottom Layer w0.114: J2.83@131.7,155.719 v3(133.248,155.719)
B35_L2_N: J2.79 J3.79 R48.1 U1.A20 | length 43.7
  Top Layer w0.089: U1.A20@121.265,144.165 v2(121.665,143.765) ; J3.79@131.9,153.719 133.121,153.719 v3(133.248,153.592)
  ART10 w0.099: v1(121.265,143.365) 121.056,143.156 121.056,142.977 121.183,142.85 121.437,142.85 121.666,143.078 123.419,143.078 123.65,143.309 124.041,143.309 124.409,143.677 124.409,144.018 124.536,144.145 124.892,144.145 125.021,144.015 125.021,143.649 125.313,143.358 126.327,143.358 126.457,143.227 126.457,142.888 126.747,142.598 127.292,142.598 127.394,142.7 127.397,142.7 127.559,142.862 127.559,143.216 127.702,143.36 128.562,143.36 129.995,144.792 129.995,145.228 129.707,145.517 127.254,145.517 127.147,145.624 127.147,145.878 127.296,146.027 129.426,146.027 129.715,146.316 129.715,146.774 129.424,147.066 128.651,147.066 128.524,147.193 128.524,147.396 128.654,147.526 129.451,147.526 129.766,147.84 129.766,148.374 129.5,148.641 129.246,148.641 128.966,148.92 128.194,148.92 128.092,149.022 128.092,149.25 128.222,149.38 128.689,149.38 128.979,149.669 128.979,150.229 128.701,150.506 128.245,150.506 128.143,150.608 128.143,150.836 128.261,150.955 128.678,150.955 129.004,151.281 129.004,151.676 128.701,151.979 128.321,151.979 128.194,152.106 128.194,152.298 128.323,152.428 128.639,152.428 128.93,152.72 128.93,153.975 129.21,154.254 130.542,154.254 130.736,154.06 130.736,153.022 131.051,152.707 131.534,152.707 131.851,153.024 131.851,153.935 131.993,154.076 132.185,154.076 132.494,153.767 133.073,153.767 v3(133.248,153.592)
  GND02 w0.109: v1(121.265,143.365) v2(121.665,143.765)
  Bottom Layer w0.114: J2.79@131.7,153.719 133.121,153.719 v3(133.248,153.592)
B35_L2_P: J2.80 J3.80 R48.2 U1.B19 | length 43.7
  Top Layer w0.089: U1.B19@120.465,144.965 v2(120.865,144.565) ; J3.80@131.9,154.219 v3(133.248,154.219)
  ART10 w0.099: v1(120.465,144.165) 120.821,143.809 123.399,143.809 123.622,143.586 123.927,143.586 124.132,143.792 124.132,144.133 124.422,144.422 125.006,144.422 125.298,144.13 125.298,143.764 125.428,143.634 126.442,143.634 126.734,143.342 126.734,143.003 126.862,142.875 127.178,142.875 127.279,142.977 127.282,142.977 127.282,143.331 127.588,143.637 128.448,143.637 129.718,144.907 129.718,145.114 129.592,145.24 127.139,145.24 126.87,145.509 126.87,145.993 127.181,146.304 129.311,146.304 129.438,146.431 129.438,146.66 129.309,146.789 128.536,146.789 128.247,147.078 128.247,147.511 128.539,147.803 129.337,147.803 129.489,147.955 129.489,148.26 129.385,148.364 129.131,148.364 128.852,148.643 128.079,148.643 127.815,148.907 127.815,149.365 128.107,149.657 128.575,149.657 128.702,149.784 128.702,150.114 128.586,150.229 128.13,150.229 127.866,150.493 127.866,150.951 128.147,151.232 128.564,151.232 128.727,151.395 128.727,151.562 128.586,151.703 128.206,151.703 127.917,151.992 127.917,152.413 128.209,152.705 128.524,152.705 128.654,152.834 128.654,154.089 129.095,154.531 130.657,154.531 131.013,154.174 131.013,153.137 131.166,152.984 131.42,152.984 131.575,153.139 131.575,154.05 131.878,154.353 132.3,154.353 132.609,154.044 133.073,154.044 v3(133.248,154.219)
  GND02 w0.109: v1(120.465,144.165) v2(120.865,144.565)
  Bottom Layer w0.114: J2.80@131.7,154.219 v3(133.248,154.219)
B35_L3_N: J2.76 J3.76 R51.1 U1.D18 | length 43.7
  Top Layer w0.089: U1.D18@118.865,145.765 v2(119.265,145.365) ; J3.76@131.9,152.219 133.121,152.219 v3(133.248,152.092)
  ART10 w0.099: v1(118.865,144.965) 118.694,144.794 118.694,144.501 118.695,144.499 118.695,143.283 118.24,142.827 118.24,141.516 118.605,141.15 119.266,141.15 119.581,141.465 119.581,141.729 119.761,141.91 120.457,141.91 120.638,142.09 121.399,142.09 121.516,141.973 121.516,141.774 121.31,141.568 121.31,141.086 121.678,140.719 122.72,140.719 123.111,141.109 123.111,141.755 123.215,141.859 123.469,141.859 123.622,141.707 123.622,140.909 123.964,140.566 124.371,140.566 124.686,140.881 124.686,142.376 124.855,142.545 125.055,142.545 125.247,142.353 125.247,140.934 125.565,140.617 126.048,140.617 126.388,140.957 126.388,141.468 126.677,141.757 127.069,141.757 127.575,141.252 129.02,141.252 129.334,141.567 129.334,141.985 129.056,142.263 128.425,142.263 128.295,142.392 128.295,142.556 128.437,142.697 128.918,142.697 130.96,144.739 130.96,147.104 130.48,147.585 130.48,148.042 130.962,148.525 130.962,151.841 131.089,151.968 132,151.968 132.254,152.222 132.537,152.222 132.639,152.121 132.639,151.714 132.766,151.587 133.248,151.587 133.401,151.74 133.401,151.94 v3(133.248,152.092)
  GND02 w0.109: v1(118.865,144.965) v2(119.265,145.365)
  Bottom Layer w0.114: J2.76@131.7,152.219 133.121,152.219 v3(133.248,152.092)
B35_L3_P: J2.77 J3.77 R51.2 U1.E17 | length 43.9
  Top Layer w0.089: U1.E17@118.065,146.565 v2(118.465,146.165) ; J3.77@131.9,152.719 133.185,152.719 v3(133.248,152.656)
  ART10 w0.099: v1(118.065,145.765) 118.293,145.765 118.72,145.339 119.05,145.339 119.278,145.11 119.278,144.729 118.972,144.423 118.972,143.168 118.516,142.712 118.516,141.63 118.72,141.427 119.151,141.427 119.304,141.58 119.304,141.844 119.646,142.187 120.343,142.187 120.523,142.367 121.514,142.367 121.793,142.088 121.793,141.659 121.587,141.454 121.587,141.201 121.793,140.995 122.606,140.995 122.834,141.224 122.834,141.87 123.101,142.136 123.584,142.136 123.899,141.821 123.899,141.023 124.079,140.843 124.257,140.843 124.409,140.995 124.409,142.49 124.74,142.822 125.17,142.822 125.524,142.468 125.524,141.049 125.679,140.894 125.933,140.894 126.111,141.072 126.111,141.583 126.562,142.034 127.184,142.034 127.689,141.529 128.905,141.529 129.057,141.681 129.057,141.87 128.942,141.986 128.31,141.986 128.019,142.278 128.019,142.671 128.322,142.974 128.803,142.974 130.683,144.854 130.683,146.99 130.203,147.47 130.203,148.157 130.686,148.64 130.686,151.956 130.975,152.245 131.886,152.245 132.14,152.499 133.092,152.499 v3(133.248,152.656)
  GND02 w0.109: v1(118.065,145.765) v2(118.465,146.165)
  Bottom Layer w0.114: J2.77@131.7,152.719 133.248,152.719 v3(133.248,152.656)
B35_L4_N: J2.73 J3.73 R95.1 U1.D20 | length 43.8
  Top Layer w0.089: U1.D20@118.865,144.165 v2(119.265,143.765) ; J3.73@131.9,150.719 133.121,150.719 v3(133.248,150.592)
  ART10 w0.099: v1(118.542,140.056) 118.745,140.259 119.163,140.259 119.281,140.141 119.281,139.814 119.573,139.522 119.841,139.522 120.295,139.068 120.856,139.068 121.313,139.525 124.045,139.525 124.296,139.776 125.527,139.776 125.679,139.624 125.679,139.344 125.55,139.215 124.777,139.215 124.259,138.697 124.259,138.05 124.537,137.772 125.529,137.772 125.809,138.052 126.72,138.052 127,138.332 127,138.594 127.116,138.709 127.254,138.709 127.368,138.596 127.368,138.179 127.673,137.874 128.385,137.874 129.029,138.519 129.029,138.904 128.75,139.183 128.75,139.688 128.382,140.056 127.065,140.056 126.924,140.197 126.924,140.386 127.051,140.513 128.854,140.513 129.088,140.746 129.428,140.746 130.175,141.493 130.175,142.991 131.604,144.421 131.604,150.578 131.793,150.767 133.073,150.767 v3(133.248,150.592)
  GND02 w0.089: v1(118.542,140.056) 119.05,140.564 119.05,141.757 118.618,142.189 118.618,142.824 119.265,143.471 v2(119.265,143.765)
  Bottom Layer w0.114: J2.73@131.7,150.719 133.058,150.719 133.185,150.592 v3(133.248,150.592)
B35_L4_P: J2.74 J3.74 R95.2 U1.D19 | length 43.8
  Top Layer w0.089: U1.D19@118.865,144.965 v2(119.265,144.565) ; J3.74@131.9,151.219 v3(133.248,151.219)
  ART10 w0.099: v1(118.542,140.716) 118.722,140.536 119.277,140.536 119.558,140.255 119.558,139.929 119.687,139.799 119.955,139.799 120.41,139.344 120.741,139.344 121.198,139.802 123.93,139.802 124.181,140.053 125.641,140.053 125.956,139.738 125.956,139.23 125.664,138.938 124.892,138.938 124.536,138.582 124.536,138.165 124.652,138.049 125.415,138.049 125.694,138.328 126.605,138.328 126.723,138.447 126.723,138.708 127.001,138.986 127.369,138.986 127.644,138.711 127.644,138.294 127.787,138.151 128.27,138.151 128.753,138.633 128.753,138.789 128.473,139.069 128.473,139.573 128.267,139.779 126.95,139.779 126.647,140.082 126.647,140.5 126.936,140.79 128.676,140.79 128.91,141.023 129.314,141.023 129.898,141.608 129.898,143.106 131.327,144.535 131.327,150.693 131.679,151.044 133.073,151.044 v3(133.248,151.219)
  GND02 w0.089: v1(118.542,140.716) 118.796,140.97 118.796,141.63 118.364,142.062 118.364,142.951 118.872,143.459 118.872,144.172 v2(119.265,144.565)
  Bottom Layer w0.114: J2.74@131.7,151.219 v3(133.248,151.219)
B35_L5_N: J2.70 J3.70 R103.1 U1.E19 | length 43.8
  Top Layer w0.089: U1.E19@118.065,144.965 v2(118.465,144.565) ; J3.70@131.9,149.219 133.121,149.219 v3(133.248,149.092)
  ART10 w0.099: v1(118.065,144.165) 118.065,143.973 117.729,143.637 117.551,143.637 117.399,143.789 117.094,143.789 116.909,143.605 116.909,142.752 116.563,142.405 116.563,141.795 116.827,141.531 116.964,141.531 117.17,141.326 117.17,140.868 117.043,140.741 116.868,140.741 116.865,140.739 116.37,140.739 116.03,140.399 116.03,139.839 116.347,139.522 116.916,139.522 117.147,139.291 117.147,138.519 117.439,138.227 118.172,138.227 118.302,138.097 118.302,137.757 118.592,137.467 118.985,137.467 119.278,137.76 119.278,138.099 119.405,138.227 119.944,138.227 120.075,138.097 120.075,137.757 120.365,137.467 120.758,137.467 121.05,137.76 121.05,138.099 121.178,138.227 121.341,138.227 121.472,138.097 121.472,137.757 121.762,137.467 122.155,137.467 122.447,137.76 122.447,138.246 122.58,138.379 122.911,138.379 123.06,138.23 123.06,137.407 123.431,137.036 128.574,137.036 129.845,138.307 129.845,139.929 130.076,140.16 130.671,140.16 131.033,140.522 131.033,142.732 132.239,143.938 132.239,148.912 132.595,149.267 133.073,149.267 v3(133.248,149.092)
  GND02 w0.109: v1(118.065,144.165) v2(118.465,144.565)
  Bottom Layer w0.114: J2.70@131.7,149.219 133.121,149.219 v3(133.248,149.092)
B35_L5_P: J2.71 J3.71 R103.2 U1.E18 | length 43.8
  Top Layer w0.089: U1.E18@118.065,145.765 v2(118.465,145.365) ; J3.71@131.9,149.719 v3(133.248,149.719)
  ART10 w0.099: 117.083,141.808 117.083,141.805 ; v1(118.065,144.965) 117.958,144.858 117.958,144.678 118.085,144.551 118.212,144.551 118.44,144.323 118.44,143.891 116.84,142.291 116.84,141.91 116.942,141.808 117.079,141.808 117.083,141.805 ; v3(133.248,149.719) 133.073,149.544 132.48,149.544 131.962,149.026 131.962,144.053 130.756,142.847 130.756,140.637 130.556,140.437 129.961,140.437 129.568,140.043 129.568,138.421 128.459,137.312 123.546,137.312 123.337,137.521 123.337,138.345 123.025,138.656 122.466,138.656 122.17,138.361 122.17,137.874 122.04,137.744 121.876,137.744 121.749,137.872 121.749,138.211 121.456,138.504 121.063,138.504 120.773,138.214 120.773,137.874 120.643,137.744 120.479,137.744 120.352,137.872 120.352,138.211 120.059,138.504 119.291,138.504 119.001,138.214 119.001,137.874 118.871,137.744 118.707,137.744 118.579,137.872 118.579,138.211 118.287,138.504 117.554,138.504 117.424,138.633 117.424,139.406 117.031,139.799 116.462,139.799 116.307,139.954 116.307,140.284 116.484,140.462 116.98,140.462 116.983,140.465 117.158,140.465 117.447,140.754 117.447,141.44 117.083,141.805
  GND02 w0.109: v1(118.065,144.965) v2(118.465,145.365)
  Bottom Layer w0.114: J2.71@131.7,149.719 v3(133.248,149.719)
B35_L6_N: J2.67 J3.67 R108.1 U1.F17 | length 43.9
  Top Layer w0.089: U1.F17@117.265,146.565 v2(117.665,146.165) ; J3.67@131.9,147.719 133.185,147.719 v3(133.248,147.656)
  ART10 w0.099: v1(117.265,145.765) 117.265,146.043 117.678,146.456 117.678,146.685 117.417,146.946 115.501,146.946 115.249,146.695 115.249,139.212 117.758,136.703 118.215,136.703 118.594,136.324 129.209,136.324 131.851,138.967 131.851,142.498 132.821,143.467 132.821,147.546 132.823,147.549 132.823,147.708 132.944,147.828 133.076,147.828 v3(133.248,147.656)
  GND02 w0.109: v1(117.265,145.765) v2(117.665,146.165)
  Bottom Layer w0.114: J2.67@131.7,147.719 133.185,147.719 v3(133.248,147.656)
B35_L6_P: J2.68 J3.68 R108.2 U1.F16 | length 44
  Top Layer w0.089: U1.F16@117.265,147.365 v2(117.665,146.965) ; J3.68@131.9,148.219 133.185,148.219 v3(133.248,148.283)
  ART10 w0.099: v1(117.265,146.565) 116.859,146.159 116.263,146.159 116.085,145.981 116.085,142.933 115.951,142.799 115.672,142.799 115.526,142.653 115.526,142.462 115.646,142.342 115.9,142.342 116.027,142.215 116.027,142.062 115.926,141.961 115.653,141.961 115.526,141.834 115.526,139.326 117.873,136.98 118.33,136.98 118.708,136.601 129.094,136.601 131.575,139.082 131.575,142.612 132.544,143.582 132.544,148.495 132.766,148.717 133.506,148.717 133.909,148.314 133.909,148.158 133.706,147.955 133.576,147.955 v3(133.248,148.283)
  GND02 w0.109: v1(117.265,146.565) v2(117.665,146.965)
  Bottom Layer w0.114: J2.68@131.7,148.219 133.185,148.219 v3(133.248,148.283)
B35_L7_N: J2.64 J3.64 R111.1 U1.M20 | length 43.8
  Top Layer w0.089: v2(112.065,143.765) U1.M20@112.465,144.165 ; J3.64@131.9,146.219 133.121,146.219 v3(133.248,146.092)
  ART05 w0.099: v1(112.268,139.522) 112.522,139.776 112.914,139.776 113.344,139.347 114.633,139.347 115.034,139.748 115.034,140.507 115.218,140.691 115.303,140.691 115.48,140.513 115.48,139.677 115.811,139.347 116.255,139.347 116.583,139.675 116.583,140.573 116.751,140.741 116.966,140.741 117.131,140.576 117.131,139.677 117.462,139.347 119.012,139.347 119.352,139.687 119.352,141.679 119.583,141.91 120.537,141.91 120.842,142.215 121.412,142.215 121.564,142.062 121.564,141.605 120.523,140.564 120.523,139.918 120.942,139.499 122.924,139.499 123.289,139.865 123.289,140.539 125.853,143.104 128.992,143.104 132.328,146.44 132.901,146.44 v3(133.248,146.092)
  GND02 w0.089: v2(112.065,143.765) 112.065,143.459 111.76,143.154 111.76,141.986 112.903,140.843 112.903,140.157 v1(112.268,139.522)
  Bottom Layer w0.114: J2.64@131.7,146.219 133.121,146.219 v3(133.248,146.092)
B35_L7_P: J2.65 J3.65 R111.2 U1.M19 | length 43.9
  Top Layer w0.089: v2(112.065,144.565) U1.M19@112.465,144.965 ; J3.65@131.9,146.719 v3(133.248,146.719)
  ART05 w0.099: v1(112.268,140.233) 112.268,140.183 112.402,140.048 112.407,140.053 113.029,140.053 113.458,139.624 114.518,139.624 114.757,139.863 114.757,140.621 115.103,140.967 115.417,140.967 115.757,140.627 115.757,139.792 115.926,139.624 116.14,139.624 116.306,139.79 116.306,140.688 116.636,141.018 117.08,141.018 117.408,140.69 117.408,139.792 117.577,139.624 118.897,139.624 119.075,139.802 119.075,141.793 119.469,142.187 120.422,142.187 120.727,142.491 121.527,142.491 121.841,142.177 121.841,141.49 120.8,140.449 120.8,140.033 121.056,139.776 122.809,139.776 123.012,139.979 123.012,140.654 125.739,143.38 128.877,143.38 132.213,146.717 133.246,146.717 v3(133.248,146.719)
  GND02 w0.089: v2(112.065,144.565) 111.665,144.165 111.665,143.44 111.506,143.281 111.506,141.834 112.649,140.691 112.649,140.284 112.598,140.233 v1(112.268,140.233)
  Bottom Layer w0.114: J2.65@131.7,146.719 v3(133.248,146.719)
B35_L8_N: J2.61 J3.61 R114.1 U1.M18 | length 42.8
  Top Layer w0.089: v2(112.065,145.365) U1.M18@112.465,145.765 ; J3.61@131.9,144.719 133.185,144.719 v3(133.248,144.656)
  ART05 w0.099: v1(111.665,144.965) 111.759,145.059 112.471,145.059 113.03,144.501 113.03,143.144 113.5,142.674 116.152,142.674 116.281,142.545 116.281,142.011 116.154,141.884 113.741,141.884 113.106,141.249 112.257,141.249 111.559,140.551 111.559,139.179 112.509,138.229 122.797,138.229 123.886,139.319 124.346,139.319 126.66,141.633 129.223,141.633 132.576,144.986 132.918,144.986 v3(133.248,144.656)
  GND02 w0.109: v1(111.665,144.965) v2(112.065,145.365)
  Bottom Layer w0.114: J2.61@131.7,144.719 133.185,144.719 v3(133.248,144.656)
